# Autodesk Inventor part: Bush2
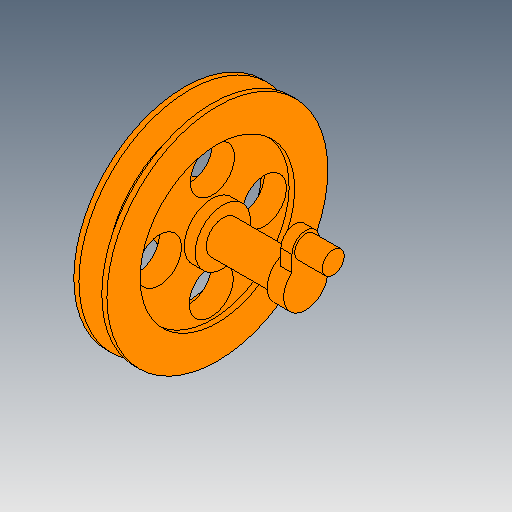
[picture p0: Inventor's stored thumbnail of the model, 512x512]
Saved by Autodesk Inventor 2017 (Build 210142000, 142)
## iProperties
Created: 2015-03
Part Number: Bush2
Document SubType Name: Modeling
Designer: Administrator
Density: 1 g/cm^3
Mass: 5.00413 g
Surface Area: 46.6393 cm^2
Volume: 5.00413 cm^3
Material: Generic
Appearance: LED - Yellow On
Author: Administrator
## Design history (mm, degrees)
sketch "Sketch1"
  geometry: L1 (0, 0)-(0, 3); L2 (5, 5)-(5, -5); L3 (5, -5)-(-5, -5); L4 (-5, -5)-(-5, 5); L5 (-5, 5)-(5, 5); 2 further points
  constraints: 10 end point, 2 coincident, 1 vertical, 1 vertical alignment, 12 other
  dimensions: "d0" = 3 distance of L1.start L1.end; "d5" = 10 distance of L4.end L2.start
extrude "Extrusion1" new body sketch "Sketch1" stored distance "d6" = 16; taper "d7" = 0 deg
sketch "Sketch2"
  geometry: L1 (-5, -5)-(-5, 5) reference; L2 (-5, 0)-(-18, 0); L3 (-18, 0)-(-18, 3); L4 (-18, 3)-(-6, 3); L5 (-6, 3)-(-6, 4); L6 (-6, 4)-(-5, 4); L7 (-5, 4)-(-5, 0)
  constraints: 12 end point, 3 parallel, 2 perpendicular, 1 collinear, 1 midpoint, 1 point on line
  dimensions: "d8" = 1 distance of L5.end L6.end; "d9" = 12 distance of L3.end L4.end; "d10" = 3 distance of L2.end L3.end; "d11" = 1 distance of L4.end L5.end
revolve "Revolution2" sketch "Sketch2" stored, may be unused: angle "d12" = 90 deg
sketch "Sketch4"
  geometry: C1 r 3 at (0, 0) reference; C2 r 2.5 at (0, 0)
  constraints: 1 centre point
  dimensions: "d18" = 5 diameter of C2
extrude "Extrusion3" join sketch "Sketch4" distance "d19" = 8; taper "d20" = 0 deg
chamfer "Chamfer1" distance "d21" = 0.5; stored, may be unused: second distance "d22" = 2, angle "d23" = 45 deg
sketch "Sketch5"
  geometry: L1 (1.8, 1.8)-(1.8, -1.8); L2 (1.8, -1.8)-(-1.8, -1.8); L3 (-1.8, -1.8)-(-1.8, 1.8); L4 (-1.8, 1.8)-(1.8, 1.8); C1 r 2 at (0, 0) reference; C2 r 3.347 at (0, 0); 1 further point
  constraints: 8 end point, 2 coincident, 1 centre point, 9 other
  dimensions: "d24" = 3.6 distance of L3.end L1.start
extrude "Extrusion4" cut sketch "Sketch5" distance "d25" = 7; taper "d26" = 0 deg
sketch "Sketch6"
  geometry: L1 (5, -5)-(-5, -5) reference; L2 (5, 5)-(5, -5) reference; L3 (-5, 5)-(5, 5) reference; L4 (-5, -5)-(-5, 5) reference; C1 r 3 at (0, 0) reference; 1 further point
extrude "Extrusion5" cut sketch "Sketch6" stored distance "d27" = 10; taper "d28" = 0 deg
sketch "Sketch7"
  geometry: L1 (0, 0)-(0, 6); C1 r 2 at (0, 6)
  constraints: 2 end point, 1 centre point, 1 coincident, 1 vertical
  dimensions: "d29" = 6 distance of L1.start L1.end; "d30" = 4 diameter of C1
extrude "Extrusion6" join sketch "Sketch7" distance "d31" = 7; taper "d32" = 0 deg
sketch "Sketch8"
  geometry: L1 (-2.5, 6)-(-2.5, 3.122); L2 (2.5, 6)-(2.5, 3.122); C1 r 2 at (0, 6) reference; A1 r 4 centre (0, 0) between (-2.5, 3.122) and (2.5, 3.122) reference; A2 r 2.5 centre (0, 6) between (2.5, 6) and (-2.5, 6); 2 further points
  constraints: 4 end point, 4 point on circle, 2 coincident, 1 centre point, 1 tangent, 1 vertical, 3 other
  dimensions: "d33" = 5 diameter of A2
extrude "Extrusion7" join sketch "Sketch8" distance "d34" = 2; taper "d35" = 0 deg
sketch "Sketch9"
  geometry: L1 (-18, -2.5)-(-18, 2.5) reference; L2 (-25.5, 2.5)-(-25.5, -2.5) reference; L3 (-26, -2)-(-26, 2) reference; L4 (-26, 0)-(-18, 0); L5 (-22, 0)-(-22, 20); L6 (-22, 20)-(-19, 20); L7 (-19, 20)-(-19, 5); L8 (-19, 5)-(-18, 5); L9 (-18, 5)-(-18, 0); L10 (-18, -3)-(-18, 3) reference; L11 (-22, 16)-(-21, 16); L12 (-21, 16)-(-19.928, 20); L13 (-19.928, 20)-(-19, 20); L14 (-19, 20)-(-19, 14); L15 (-20, 14)-(-19, 14); L16 (-20, 14)-(-20, 5); L17 (-20, 5)-(-18, 5); L18 (-18, 5)-(-18, 0); L19 (-24, 5)-(-26, 5); L20 (-26, 5)-(-26, 0); L21 (-26, 5)-(-26, 0); L22 (-24, 14)-(-24, 5); L23 (-25, 20)-(-25, 5); L24 (-22, 16)-(-23, 16); L25 (-25, 20)-(-25, 14); L26 (-24.072, 20)-(-25, 20); L27 (-23, 16)-(-24.072, 20); L28 (-22, 20)-(-25, 20); L29 (-24, 14)-(-25, 14); L30 (-25, 5)-(-26, 5); L31 (-18, 2.5)-(-25.5, 2.5) reference; L32 (-18, -2.5)-(-18, 2.5) reference; L33 (-18, 2.5)-(-26, 2.5); L34 (-26, 2.5)-(-26, 5); L35 (-18, 2.5)-(-18, 5); L36 (-31.6, 0)-(7.6, 0) reference; 1 further point
  constraints: 58 end point, 8 symmetric about line, 6 perpendicular, 5 point on line, 4 collinear, 4 midpoint, 2 vertical
  dimensions: "d36" = 20 distance of L5.start L5.end; "d37" = 15 deg angle of L5 L12; "d38" = 3 distance between parallel lines of L5 L7; "d39" = 5 distance between parallel lines of L4 L8; "d40" = 4 distance between parallel lines of L6 L11; "d41" = 1 distance from line of L5 L11.end; "d42" = 1 distance between parallel lines of L16 L7; "d43" = 2 distance between parallel lines of L11 L15
revolve "Revolution3" sketch "Sketch9" stored, may be unused: angle "d44" = 90 deg
sketch "Sketch10"
  geometry: L1 (-0.106, 4.999)-(-0.106, 14); C1 r 4 at (-0.106, 9.499); 4 further points
  constraints: 2 end point, 1 centre point, 1 midpoint, 1 vertical, 6 other
  dimensions: "d45" = 8 diameter of C1
extrude "Extrusion8" cut sketch "Sketch10" stored distance "d46" = 2; taper "d47" = 0 deg
pattern_circular "Circular Pattern1" dims angle "d49" = 360 deg
body "Solid1"
node "Projected Loop1"
node "Projected Loop2"
node "Projected Loop3"
